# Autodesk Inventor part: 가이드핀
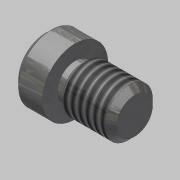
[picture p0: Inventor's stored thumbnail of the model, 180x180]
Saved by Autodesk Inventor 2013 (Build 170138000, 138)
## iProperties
Created: 2019-02
Part Number: 가이드핀
Material: 스테인리스강
Document SubType Name: Modeling
Designer: mduedu
Density: 1 g/cm^3
Author: mduedu
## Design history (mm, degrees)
sketch "스케치1"
  geometry: C1 r 5.5 at (0, 0); 1 further point
  constraints: 1 centre point, 1 coincident
  dimensions: "d0" = 11 diameter of C1
extrude "돌출1" new body sketch "스케치1" distance "d1" = 5; taper "d2" = 0 deg
sketch "스케치2"
  geometry: C1 r 3 at (0, 0); 1 further point
  constraints: 1 centre point, 1 coincident
  dimensions: "d3" = 6 diameter of C1
extrude "돌출2" join sketch "스케치2" distance "d4" = 1; taper "d5" = 0 deg
sketch "스케치3"
  geometry: C1 r 4 at (0, 0); 1 further point
  constraints: 1 centre point, 1 coincident
  dimensions: "d6" = 8 diameter of C1
extrude "돌출3" join sketch "스케치3" distance "d7" = 9; taper "d8" = 0 deg
chamfer "모따기1" distance "d9" = 1; stored, may be unused: second distance "d10" = 2, angle "d11" = 45 deg
feature "스레드1" dims "d12" = 10, "d13" = 0
node "솔리드1"
